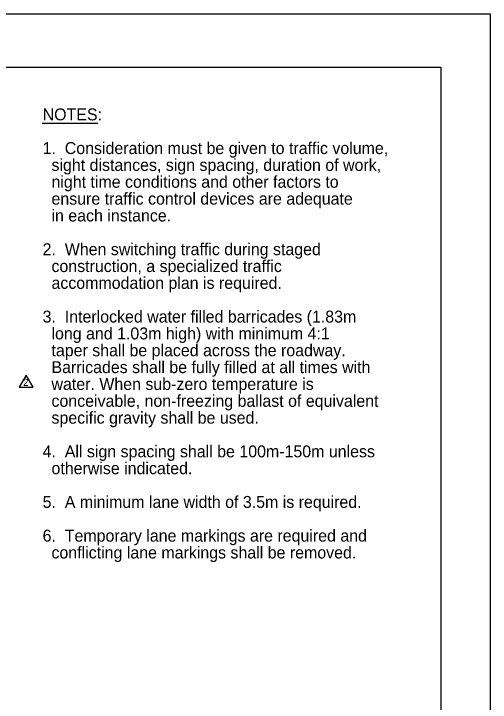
# Model space of a CAD drawing. Extents: x 2170 to 2386, y 134 to 413.
# Drawn here: x 2288.9 to 2385.6, y 273.1 to 412.8 of the extents above; entities that cross this region are included whole.
import ezdxf

# ---------------------------------------------------------------- set-up
doc = ezdxf.new("R2010")
doc.units = 0
for name, color, linetype in [('Level 10', 7, 'Continuous'), ('Level 44', 7, 'Continuous'), ('Level 60', 7, 'Continuous'), ('Level 63', 7, 'Continuous')]:
    doc.layers.add(name, color=color, linetype=linetype)

msp = doc.modelspace()

# ---------------------------------------------------------------- linework, layer by layer
at = {"layer": 'Level 10'}
msp.add_line((2294.68, 390.53), (2305.97, 390.53), dxfattribs=at)
at = {"layer": 'Level 60'}
for points in [[(2169.62, 412.76), (2385.62, 412.76), (2385.62, 133.76), (2169.62, 133.76)], [(2188.75, 401.95), (2375.62, 401.95), (2375.62, 144.57), (2188.75, 144.57)]]:
    msp.add_lwpolyline(points, close=True, dxfattribs=at)
at = {"layer": 'Level 63'}
for points in [[(2291.46, 339.44), (2290.07, 337.01)], [(2292.86, 337.01), (2291.46, 339.44)], [(2290.07, 337.01), (2290.04, 336.97), (2292.88, 336.97), (2292.86, 337.01)]]:
    msp.add_lwpolyline(points, dxfattribs=at)

# ---------------------------------------------------------------- texts
at = {"layer": 'Level 10'}
for s, p in [('NOTES:', (2294.8, 391.13)), ('1.  Consideration must be given to traffic volume, ', (2294.8, 384.29)), ('  sight distances, sign spacing, duration of work,', (2294.8, 380.87)), ('  night time conditions and other factors to ', (2294.8, 377.45)), ('  ensure traffic control devices are adequate ', (2294.8, 374.03)), ('  in each instance.', (2294.8, 370.61)), ('2.  When switching traffic during staged ', (2294.8, 363.77)), ('  construction, a specialized traffic ', (2294.8, 360.35)), ('  accommodation plan is required.', (2294.8, 356.94)), ('3.  Interlocked water filled barricades (1.83m ', (2294.8, 350.1)), ('  long and 1.03m high) with minimum 4:1 ', (2294.8, 346.68)), ('  taper shall be placed across the roadway. ', (2294.8, 343.26)), ('  Barricades shall be fully filled at all times with ', (2294.8, 339.84)), ('  water. When sub-zero temperature is ', (2294.8, 336.42)), ('  conceivable, non-freezing ballast of equivalent ', (2294.8, 333)), ('  specific gravity shall be used.    ', (2294.8, 329.58)), ('4.  All sign spacing shall be 100m-150m unless', (2294.8, 322.75)), ('  otherwise indicated.', (2294.8, 319.33)), ('5.  A minimum lane width of 3.5m is required.', (2294.8, 312.49)), ('6.  Temporary lane markings are required and ', (2294.8, 305.65)), ('  conflicting lane markings shall be removed.', (2294.8, 302.23))]:
    msp.add_text(s, height=2.419, dxfattribs=at).set_placement(p)
at = {"layer": 'Level 44'}
msp.add_text('2', height=1.45, rotation=360, dxfattribs=at).set_placement((2290.84, 337.24))

doc.saveas('drawing.dxf')
